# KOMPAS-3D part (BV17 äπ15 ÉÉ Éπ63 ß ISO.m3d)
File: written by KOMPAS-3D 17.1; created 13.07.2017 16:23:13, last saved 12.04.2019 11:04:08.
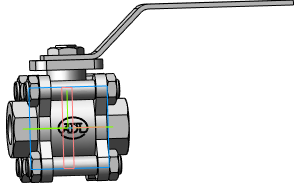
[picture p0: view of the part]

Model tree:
1. Операция без истории:2  (labels: Сталь 20  ГОСТ 1050-88)

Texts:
  DISO1
  DISO2
  BV17 Ду8 1/4" Ру63 с ISO
  BV17 Ду8 СС Ру63 с ISO
  BV17 Ду10 3/8" Ру63 с ISO
  BV17 Ду10 СС Ру63 с ISO
  BV17 Ду15 1/2" Ру63 с ISO
  BV17 Ду15 СС Ру63 с ISO
  BV17 Ду15 ФФ Ру40 с ISO
  BV17 Ду20 3/4" Ру63 с ISO
  BV17 Ду20 СС Ру40 с ISO
  BV17 Ду20 ФФ Ру40 с ISO
  BV17 Ду25 1" Ру63 с ISO
  BV17 Ду25 СС Ру63 с ISO
  BV17 Ду25 ФФ Ру40 с ISO
  BV17 Ду32 1 1/4" Ру63 с ISO
  BV17 Ду32 СС Ру63 с ISO
  BV17 Ду32 ФФ Ру40 с ISO
  BV17 Ду40 1 1/2" Ру63 с ISO
  BV17 Ду40 СС Ру63 с ISO
  BV17 Ду40 ФФ Ру40 с ISO
  BV17 Ду50 2" Ру63 с ISO
  BV17 Ду50 СС Ру63 с ISO
  BV17 Ду50 ФФ Ру40 с ISO
  BV17 Ду65 2 1/2" Ру40 с ISO
  BV17 Ду65 СС Ру40 с ISO
  BV17 Ду65 ФФ Ру40 с ISO
  BV17 Ду80 3" Ру40 с ISO
  BV17 Ду80 СС Ру40 с ISO
  BV17 Ду80 ФФ Ру40 с ISO
  BV17 Ду100 4" Ру40 с ISO
  BV17 Ду100 СС Ру40 с ISO
  BV17 Ду100 ФФ Ру40 с ISO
